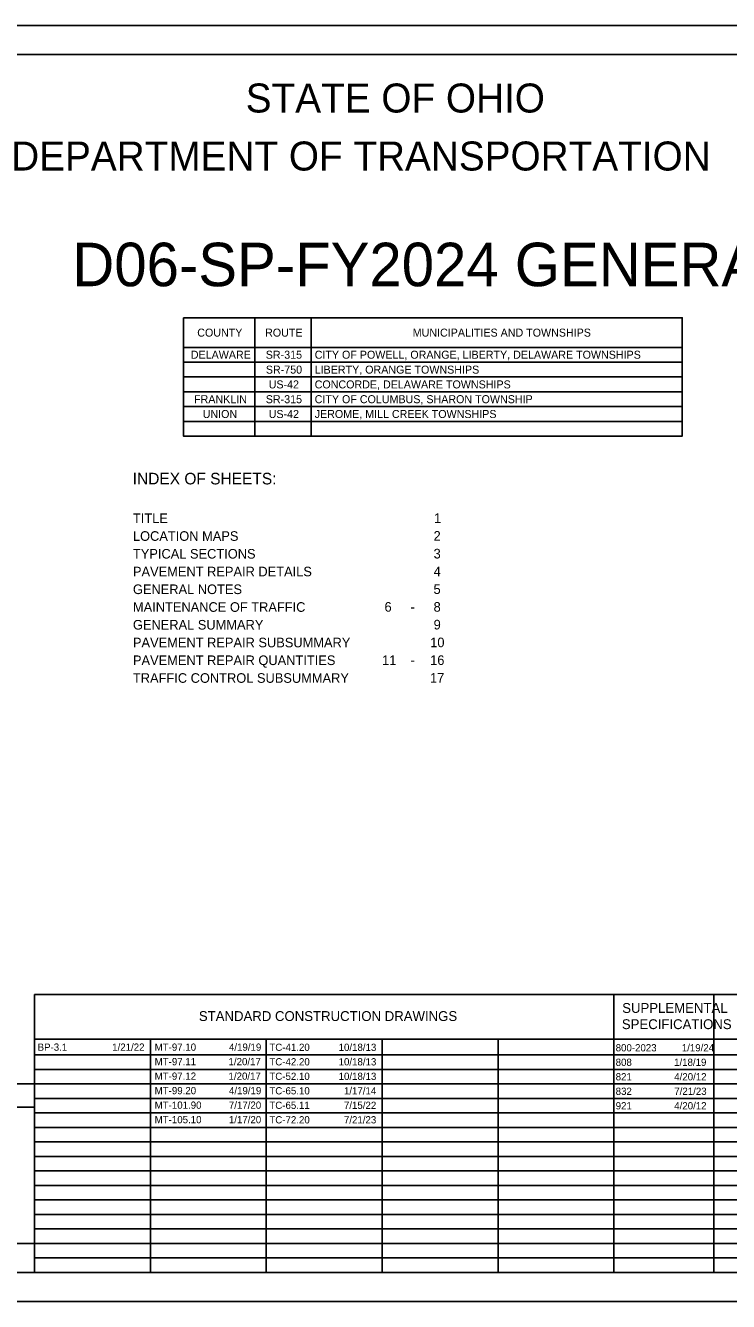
# Model space of a CAD drawing. Extents: x 0 to 34, y 0 to 22.
# Drawn here: x 9.99 to 22.13, y 0 to 22 of the extents above; entities that cross this region are included whole.
import ezdxf

# ---------------------------------------------------------------- set-up
doc = ezdxf.new("R2010")
doc.units = 0
for name, color, linetype in [('Default', 7, 'Continuous'), ('SH_Border', 7, 'Continuous'), ('SH_Cut_Line', 7, 'Continuous'), ('SH_Data', 7, 'Continuous'), ('SH_Text', 7, 'Continuous')]:
    doc.layers.add(name, color=color, linetype=linetype)

msp = doc.modelspace()

# ---------------------------------------------------------------- linework, layer by layer
at = {"layer": 'Default'}
for p, q in [((12.72, 16.96), (21.33, 16.96)), ((12.72, 16.96), (12.72, 14.92)), ((13.95, 16.96), (13.95, 14.92)), ((14.925, 16.96), (14.925, 14.92)), ((21.33, 16.96), (21.33, 14.92)), ((12.72, 16.45), (21.33, 16.45)), ((12.72, 16.195), (21.33, 16.195)), ((12.72, 15.94), (21.33, 15.94)), ((12.72, 15.685), (21.33, 15.685)), ((12.72, 15.43), (21.33, 15.43)), ((12.72, 15.175), (21.33, 15.175)), ((12.72, 14.92), (21.33, 14.92))]:
    msp.add_line(p, q, dxfattribs=at)
for points in [[(12.72, 16.96), (13.95, 16.96), (13.95, 16.45), (12.72, 16.45)], [(13.95, 16.96), (14.925, 16.96), (14.925, 16.45), (13.95, 16.45)], [(14.925, 16.96), (21.33, 16.96), (21.33, 16.45), (14.925, 16.45)], [(12.72, 16.45), (13.95, 16.45), (13.95, 16.195), (12.72, 16.195)], [(13.95, 16.45), (14.925, 16.45), (14.925, 16.195), (13.95, 16.195)], [(14.925, 16.45), (21.33, 16.45), (21.33, 16.195), (14.925, 16.195)], [(12.72, 16.195), (13.95, 16.195), (13.95, 15.94), (12.72, 15.94)], [(13.95, 16.195), (14.925, 16.195), (14.925, 15.94), (13.95, 15.94)], [(14.925, 16.195), (21.33, 16.195), (21.33, 15.94), (14.925, 15.94)], [(12.72, 15.94), (13.95, 15.94), (13.95, 15.685), (12.72, 15.685)], [(13.95, 15.94), (14.925, 15.94), (14.925, 15.685), (13.95, 15.685)], [(14.925, 15.94), (21.33, 15.94), (21.33, 15.685), (14.925, 15.685)], [(12.72, 15.685), (13.95, 15.685), (13.95, 15.43), (12.72, 15.43)], [(13.95, 15.685), (14.925, 15.685), (14.925, 15.43), (13.95, 15.43)], [(14.925, 15.685), (21.33, 15.685), (21.33, 15.43), (14.925, 15.43)], [(12.72, 15.43), (13.95, 15.43), (13.95, 15.175), (12.72, 15.175)], [(13.95, 15.43), (14.925, 15.43), (14.925, 15.175), (13.95, 15.175)], [(14.925, 15.43), (21.33, 15.43), (21.33, 15.175), (14.925, 15.175)], [(12.72, 15.175), (13.95, 15.175), (13.95, 14.92), (12.72, 14.92)], [(13.95, 15.175), (14.925, 15.175), (14.925, 14.92), (13.95, 14.92)], [(14.925, 15.175), (21.33, 15.175), (21.33, 14.92), (14.925, 14.92)]]:
    msp.add_lwpolyline(points, close=True, dxfattribs=at)
at = {"layer": 'SH_Border'}
msp.add_lwpolyline([(1.5, 21.5), (33.5, 21.5), (33.5, 0.5), (1.5, 0.5)], close=True, dxfattribs=at)
at = {"layer": 'SH_Cut_Line'}
msp.add_lwpolyline([(0, 0), (34, 0), (34, 22), (0, 22)], close=True, dxfattribs=at)
at = {"layer": 'SH_Data'}
for p, q in [((10.15, 5.292), (23.6, 5.292)), ((10.15, 0.5), (10.15, 5.292)), ((20.15, 0.5), (20.15, 5.292)), ((21.875, 0.5), (21.875, 5.292)), ((10.15, 4.521), (23.6, 4.521)), ((12.15, 0.5), (12.15, 4.521)), ((14.15, 0.5), (14.15, 4.521)), ((16.15, 0.5), (16.15, 4.521)), ((18.15, 0.5), (18.15, 4.521)), ((10.15, 4.25), (23.6, 4.25)), ((10.15, 4), (23.6, 4)), ((7.35, 3.75), (10.15, 3.75)), ((10.15, 3.75), (23.6, 3.75)), ((10.15, 3.75), (10.15, 0.5)), ((7.35, 3.35), (10.15, 3.35)), ((10.15, 3.5), (23.6, 3.5)), ((10.15, 3.25), (23.6, 3.25)), ((10.15, 3), (23.6, 3)), ((10.15, 2.75), (23.6, 2.75)), ((10.15, 2.5), (23.6, 2.5)), ((10.15, 2.25), (23.6, 2.25)), ((10.15, 2), (23.6, 2)), ((10.15, 1.75), (23.6, 1.75)), ((10.15, 1.5), (23.6, 1.5)), ((10.15, 1.25), (23.6, 1.25)), ((10.15, 1), (23.6, 1)), ((10.15, 0.75), (23.6, 0.75)), ((7.35, 0.5), (10.15, 0.5))]:
    msp.add_line(p, q, dxfattribs=at)
msp.add_lwpolyline([(7.35, 0.5), (7.35, 1), (10.15, 1), (10.15, 0.5)], close=True, dxfattribs=at)

# ---------------------------------------------------------------- texts
at = {"layer": 'Default'}
for s, height, p in [('COUNTY', 0.138, (12.958, 16.636)), ('ROUTE', 0.138, (14.129, 16.636)), ('MUNICIPALITIES AND TOWNSHIPS', 0.138, (16.677, 16.636)), ('DELAWARE', 0.138, (12.847, 16.255)), ('SR-315', 0.138, (14.141, 16.255)), ('CITY OF POWELL, ORANGE, LIBERTY, DELAWARE TOWNSHIPS', 0.138, (14.985, 16.255)), ('SR-750', 0.138, (14.142, 15.998)), ('LIBERTY, ORANGE TOWNSHIPS', 0.138, (14.985, 15.998)), ('US-42', 0.138, (14.191, 15.743)), ('CONCORDE, DELAWARE TOWNSHIPS', 0.138, (14.985, 15.743)), ('FRANKLIN', 0.138, (12.903, 15.488)), ('SR-315', 0.138, (14.141, 15.488)), ('CITY OF COLUMBUS, SHARON TOWNSHIP', 0.138, (14.985, 15.488)), ('UNION', 0.138, (13.052, 15.233)), ('US-42', 0.138, (14.191, 15.233)), ('JEROME, MILL CREEK TOWNSHIPS', 0.138, (14.985, 15.233)), ('TITLE', 0.1656, (11.848, 13.421)), ('1', 0.166, (17.045, 13.423)), ('LOCATION MAPS', 0.1656, (11.848, 13.115)), ('2', 0.166, (17.037, 13.117)), ('TYPICAL SECTIONS', 0.1656, (11.848, 12.809)), ('3', 0.166, (17.037, 12.811)), ('PAVEMENT REPAIR DETAILS', 0.1656, (11.848, 12.503)), ('4', 0.166, (17.039, 12.505)), ('GENERAL NOTES', 0.1656, (11.848, 12.197)), ('5', 0.166, (17.036, 12.199)), ('MAINTENANCE OF TRAFFIC', 0.1656, (11.848, 11.891)), ('6', 0.166, (16.19, 11.893)), ('-', 0.166, (16.638, 11.893)), ('8', 0.166, (17.037, 11.893)), ('GENERAL SUMMARY', 0.1656, (11.848, 11.585)), ('9', 0.166, (17.038, 11.587)), ('PAVEMENT REPAIR SUBSUMMARY', 0.1656, (11.848, 11.279)), ('10', 0.1656, (16.979, 11.281)), ('PAVEMENT REPAIR QUANTITIES', 0.1656, (11.848, 10.973)), ('11', 0.1656, (16.149, 10.975)), ('-', 0.166, (16.638, 10.975)), ('16', 0.1656, (16.978, 10.975)), ('TRAFFIC CONTROL SUBSUMMARY', 0.1656, (11.848, 10.667)), ('17', 0.1656, (16.975, 10.669)), ('BP-3.1', 0.125, (10.203, 4.323)), ('1/21/22', 0.125, (11.49, 4.323)), ('MT-97.10', 0.125, (12.223, 4.323)), ('4/19/19', 0.125, (13.506, 4.323)), ('TC-41.20', 0.125, (14.203, 4.32)), ('10/18/13', 0.125, (15.398, 4.32)), ('800-2023', 0.125, (20.18, 4.312)), ('1/19/24', 0.125, (21.321, 4.312)), ('MT-97.11', 0.125, (12.223, 4.073)), ('1/20/17', 0.125, (13.498, 4.073)), ('TC-42.20', 0.125, (14.203, 4.07)), ('10/18/13', 0.125, (15.398, 4.07)), ('808', 0.125, (20.18, 4.062)), ('1/18/19', 0.125, (21.188, 4.062)), ('MT-97.12', 0.125, (12.223, 3.823)), ('1/20/17', 0.125, (13.498, 3.823)), ('TC-52.10', 0.125, (14.203, 3.82)), ('10/18/13', 0.125, (15.398, 3.82)), ('821', 0.125, (20.18, 3.812)), ('4/20/12', 0.125, (21.191, 3.812)), ('MT-99.20', 0.125, (12.223, 3.573)), ('4/19/19', 0.125, (13.506, 3.573)), ('TC-65.10', 0.125, (14.203, 3.57)), ('1/17/14', 0.125, (15.49, 3.57)), ('832', 0.125, (20.18, 3.562)), ('7/21/23', 0.125, (21.192, 3.562)), ('MT-101.90', 0.125, (12.223, 3.323)), ('7/17/20', 0.125, (13.504, 3.323)), ('TC-65.11', 0.125, (14.203, 3.32)), ('7/15/22', 0.125, (15.49, 3.32)), ('921', 0.125, (20.18, 3.312)), ('4/20/12', 0.125, (21.191, 3.312)), ('MT-105.10', 0.125, (12.223, 3.073)), ('1/17/20', 0.125, (13.504, 3.073)), ('TC-72.20', 0.125, (14.203, 3.07)), ('7/21/23', 0.125, (15.49, 3.07))]:
    msp.add_text(s, height=height, dxfattribs=at).set_placement(p)
at = {"layer": 'SH_Text'}
for s, height, p in [('STATE OF OHIO', 0.5, (13.795, 20.5)), ('DEPARTMENT OF TRANSPORTATION', 0.5, (9.747, 19.5)), ('D06-SP-FY2024 GENERAL', 0.75, (10.802, 17.505)), ('INDEX OF SHEETS:', 0.2, (11.844, 14.088)), ('SUPPLEMENTAL', 0.17, (20.293, 4.976)), ('STANDARD CONSTRUCTION DRAWINGS', 0.17, (12.986, 4.836)), ('SPECIFICATIONS', 0.17, (20.287, 4.696))]:
    msp.add_text(s, height=height, dxfattribs=at).set_placement(p)

doc.saveas('drawing.dxf')
